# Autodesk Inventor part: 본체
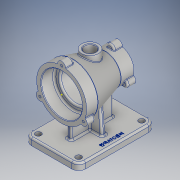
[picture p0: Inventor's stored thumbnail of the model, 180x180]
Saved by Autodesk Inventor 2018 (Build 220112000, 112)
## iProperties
Created: 2020-03
Part Number: 본체
Material: 알루미늄 6061
Document SubType Name: Modeling
Designer: Administrator
Density: 2.7 g/cm^3
Appearance: 알루미늄 - 평지
Mass: 1020.21 g
Surface Area: 863.968 cm^2
Volume: 377.855 cm^3
Author: Administrator
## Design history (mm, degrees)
sketch "스케치1"
  geometry: L1 (0, 0)-(0, 44); L2 (0, 44)-(-20, 44); L3 (-20, 44)-(-82.164, 27.5); L4 (-82.164, 27.5)-(-100, 27.5); L5 (-100, 27.5)-(-100, 0); L6 (-100, 0)-(0, 0)
  constraints: 12 end point, 3 perpendicular, 1 parallel, 1 vertical
  dimensions: "d0" = 20 distance from line of L2.end L1; "d1" = 100 distance between parallel lines of L5 L1; "d2" = 88 diameter of L2 L6; "d3" = 55 diameter of L4 L6
revolve "회전1" sketch "스케치1" stored, may be unused: angle "d4" = 90 deg
sketch "스케치2"
  geometry: L1 (0, 0)-(23, 0); L2 (23, 0)-(23, 36); L3 (23, 36)-(0, 36); L4 (0, 36)-(0, 0); L5 (23, 0)-(70, 0); L6 (70, 0)-(70, 26); L7 (70, 26)-(23, 26); L8 (23, 26)-(23, 0); L9 (100, 27.5)-(100, -27.5) reference; L10 (70, 0)-(100, 0); L11 (100, 0)-(100, 20); L12 (100, 20)-(70, 20); L13 (70, 20)-(70, 0)
  constraints: 24 end point, 6 parallel, 3 horizontal, 3 perpendicular, 1 point on line
  dimensions: "d5" = 23 distance of L2.end L3.end; "d6" = 30 distance of L11.end L12.end; "d7" = 72 diameter of L3 L1; "d8" = 52 diameter of L7 L5; "d9" = 40 diameter of L12 L10
revolve "회전2" sketch "스케치2" stored, may be unused: angle "d10" = 90 deg
chamfer "모따기1" distance "d11" = 1; stored, may be unused: second distance "d12" = 2, angle "d13" = 45 deg
fillet "모깎기1" dims "d14" = 3
fillet "모깎기2" dims "d15" = 3
node "작업 평면1"
sketch "스케치3"
  geometry: L1 (0, -44)-(0, 44) reference; L2 (-100, -27.5)-(-100, 27.5) reference; L3 (0, 0)-(-100, 0); L4 (17.5, 47.5)-(-117.5, 47.5); L5 (-117.5, 47.5)-(-117.5, -47.5); L6 (-117.5, -47.5)-(17.5, -47.5); L7 (17.5, -47.5)-(17.5, 47.5); L8 (17.5, 47.5)-(-117.5, -47.5); L9 (-117.5, 47.5)-(17.5, -47.5); 2 further points
  constraints: 14 end point, 6 midpoint, 2 parallel, 1 horizontal, 1 perpendicular
  dimensions: "d17" = 135 distance of L5.end L6.end; "d18" = 95 distance of L4.end L5.end
extrude "돌출1" join sketch "스케치3" distance "d19" = 12; taper "d20" = 0 deg
sketch "스케치4"
  geometry: L1 (117.5, 47.5)-(-17.5, 47.5) reference; L2 (-17.5, 47.5)-(-17.5, -47.5) reference; L3 (-17.5, -47.5)-(117.5, -47.5) reference; L4 (-17.5, 47.5)-(-17.5, -47.5) reference; L5 (117.5, 47.5)-(-17.5, 47.5) reference; L6 (117.5, -47.5)-(117.5, 47.5) reference; L7 (13, -4)-(87, -4); L8 (87, -4)-(87, 4); L9 (87, 4)-(13, 4); L10 (13, 4)-(13, -4); L11 (13, -4)-(87, 4); L12 (87, -4)-(13, 4); 3 further points
  constraints: 12 end point, 3 midpoint, 2 parallel, 1 horizontal, 1 horizontal alignment, 1 perpendicular
  dimensions: "d21" = 67.5 distance from line of point (50, 0) L6; "d22" = 8 distance of L7.end L8.end; "d23" = 74 distance of L8.end L9.end
extrude "돌출2" join sketch "스케치4" stored distance "d24" = 12; taper "d25" = 0 deg
node "작업 평면2"
feature "리브1" dims "d28" = 1, "d29" = 8, "d30" = 0, "d31" = 0, "d32" = 1, "d33" = 1
node "작업 평면3"
sketch "스케치6"
  geometry: L1 (17.5, -47.5)-(17.5, 47.5) reference; L2 (17.5, 0)-(-117.5, 0); L3 (-117.5, 47.5)-(-117.5, -47.5) reference; C1 r 15 at (-50, 0); 1 further point
  constraints: 3 midpoint, 2 end point, 1 centre point
  dimensions: "d35" = 30 diameter of C1
extrude "돌출3" join sketch "스케치6" stored distance "d36" = 12; taper "d37" = 0 deg
sketch "스케치7"
  geometry: C1 r 15 at (0, 0) reference; C2 r 10 at (0, 0); 1 further point
  constraints: 1 centre point, 1 coincident
  dimensions: "d38" = 20 diameter of C2
extrude "돌출4" cut sketch "스케치7" stored distance "d39" = 12; taper "d40" = 0 deg; dims "d17" = 135, "d18" = 95, "d154" = 3
chamfer "모따기2" distance "d41" = 1; stored, may be unused: second distance "d42" = 2, angle "d43" = 45 deg
fillet "모깎기3" dims "d44" = 12
fillet "모깎기4" dims "d45" = 3
fillet "모깎기5" dims "d46" = 3
fillet "모깎기6" dims "d47" = 3
fillet "모깎기7" dims "d48" = 3
fillet "모깎기8" dims "d49" = 3
fillet "모깎기9" dims "d50" = 3
fillet "모깎기10" dims "d51" = 3
fillet "모깎기11" dims "d52" = 3
fillet "모깎기12" dims "d53" = 3
sketch "스케치8"
  geometry: A1 r 12 centre (105.5, 35.5) between (117.5, 35.5) and (105.5, 47.5) reference; A2 r 12 centre (105.5, -35.5) between (105.5, -47.5) and (117.5, -35.5) reference; A3 r 12 centre (-5.5, -35.5) between (-17.5, -35.5) and (-5.5, -47.5) reference; A4 r 12 centre (-5.5, 35.5) between (-5.5, 47.5) and (-17.5, 35.5) reference; 5 further points
  constraints: 4 coincident
hole "구멍1" sketch "스케치8" at (105.5, 35.5), (105.5, -35.5), (-5.5, -35.5), (-5.5, 35.5) diameter "d54" = 10; stored, may be unused: countersink angle "d58" = 90 deg, drill point angle "d60" = 118 deg; dims "d55" = 6, "d56" = 4, "d57" = 2, "d59" = 8
sketch "스케치9"
  geometry: C1 r 44 at (0, 0); A1 r 43.9 centre (0, 0) between (6.566, -43.406) and (-6.566, -43.406) reference; A2 r 7 centre (0, 43.9) between (6.978, 43.342) and (-6.978, 43.342); 2 further points
  constraints: 6 point on circle, 2 centre point, 1 coincident, 1 vertical alignment
  dimensions: "d61" = 88 diameter of C1; "d62" = 14 diameter of A2
extrude "돌출5" join sketch "스케치9" distance "d63" = 15; taper "d64" = 0 deg
sketch "스케치10"
  geometry: A1 r 7 centre (0, 0) between (6.985, -0.458) and (-6.985, -0.458) reference; 2 further points
  constraints: 1 coincident
hole "구멍2" sketch "스케치10" at (0, 0) diameter "d68" = 4.134; stored, may be unused: countersink angle "d72" = 90 deg, drill point angle "d74" = 118 deg; dims "d69" = 9, "d70" = 4, "d71" = 2, "d73" = 11
fillet "모깎기13" dims "d78" = 1
sketch "스케치11"
  geometry: A1 r 27.5 centre (0, 0) between (6.943, 26.609) and (-6.943, 26.609); A2 r 27.5 centre (0, 0) between (6.311, -26.766) and (-6.311, -26.766) reference; A3 r 7 centre (0, 27.5) between (6.943, 26.609) and (-6.943, 26.609); 1 further point
  constraints: 6 point on circle, 2 centre point, 1 coincident
  dimensions: "d81" = 7 radius of A3
extrude "돌출6" join sketch "스케치11" distance "d82" = 15; taper "d83" = 0 deg
sketch "스케치12"
  geometry: A1 r 7 centre (0, 0) between (6.943, -0.891) and (-6.943, -0.891) reference; 2 further points
  constraints: 1 coincident
hole "구멍3" sketch "스케치12" at (0, 0) diameter "d87" = 4.134; stored, may be unused: countersink angle "d91" = 90 deg, drill point angle "d93" = 118 deg; dims "d88" = 9, "d89" = 4, "d90" = 2, "d92" = 11
fillet "모깎기14" dims "d97" = 3
fillet "모깎기15" dims "d98" = 3
fillet "모깎기16" dims "d99" = 1
sketch "스케치13"
  geometry: L1 (-17.5, 35.5)-(-17.5, -35.5) reference; L2 (-17.5, 0)-(118.541, 0); L3 (-5.5, -47.5)-(105.5, -47.5) reference; 3 further points
  constraints: 2 end point, 2 midpoint, 1 horizontal, 1 vertical alignment, 1 other
  dimensions: "d100" = 10 distance from line of point (50.521, -37.5) L3
feature "엠보싱1" sketch "스케치13" dims "d5" = 23, "d6" = 30, "d7" = 72, "d8" = 52, "d9" = 40, "d101" = 0.5, "d102" = 0
sketch "스케치14"
  geometry: 1 further point
sketch "스케치15"
  geometry: 1 further point
sketch "스케치16"
  geometry: L1 (0, 0)-(0, 44); L2 (0, 44)-(20, 44); L3 (20, 44)-(77, 27.5); L4 (77, 27.5)-(100, 27.5); L5 (100, 27.5)-(100, 0); L6 (100, 0)-(0, 0)
  constraints: 12 end point, 3 perpendicular, 1 parallel, 1 vertical
  dimensions: "d103" = 20 distance of L1.end L2.end; "d104" = 100 distance between parallel lines of L5 L1; "d105" = 77 distance from line of L3.end L1; "d106" = 88 diameter of L2 L6; "d107" = 55 diameter of L4 L6
revolve "회전3" sketch "스케치16" stored, may be unused: angle "d108" = 90 deg
sketch "스케치17"
  geometry: L1 (13, -4)-(87, -4); L2 (87, -4)-(87, 4); L3 (87, 4)-(13, 4); L4 (13, 4)-(13, -4); L5 (13, -4)-(87, 4); L6 (87, -4)-(13, 4); L7 (117.5, -35.5)-(117.5, 35.5) reference; 3 further points
  constraints: 12 end point, 3 midpoint, 2 parallel, 1 horizontal, 1 horizontal alignment, 1 perpendicular
  dimensions: "d109" = 67.5 distance from line of point (50, 0) L7; "d110" = 74 distance of L2.end L3.end; "d111" = 8 distance of L1.end L2.end
extrude "돌출7" join sketch "스케치17" stored distance "d112" = 10; taper "d113" = 0 deg
node "작업 평면4"
sketch "스케치18"
  geometry: L1 (71.029, 12.5)-(71.029, 12) reference; L2 (71.029, 12)-(80, 12) reference; L3 (83, 9)-(83, 0) reference; L4 (83, 0)-(-12, 0) reference; L5 (-12, 0)-(-12, 9) reference; L6 (-9, 12)-(31.5, 12) reference; L7 (31.5, 12)-(31.5, 51.911) reference; L8 (39.5, 51.911)-(39.5, 12) reference; L9 (39.5, 12)-(70.615, 12) reference; L10 (70.615, 12)-(70.615, 12.5) reference; L11 (70.615, 12.5)-(71.029, 12.5) reference; L12 (0, 12)-(71, 12) reference; L13 (60.5, 12)-(56.427, 58.553); L14 (71, 0)-(0, 0) reference; L15 (35.5, 0)-(35.5, 87); A1 r 3 centre (80, 9) between (83, 9) and (80, 12) reference; A2 r 3 centre (-9, 9) between (-9, 12) and (-12, 9) reference; A3 r 35.316 centre (35.5, 87) between (39.5, 51.911) and (31.5, 51.911) reference; 1 further point
  constraints: 4 end point, 1 midpoint, 1 point on circle, 1 point on line, 1 vertical
  dimensions: "d114" = 25 distance from line of L13.start L15; "d115" = 95 deg angle of L13 L9
feature "리브2" sketch "스케치18" dims "d116" = 1, "d117" = 8, "d118" = 0, "d119" = 0, "d120" = 1, "d121" = 1
sketch "스케치19"
  geometry: L1 (0, 0)-(23, 0); L2 (23, 0)-(23, 36); L3 (23, 36)-(0, 36); L4 (0, 36)-(0, 0); L5 (23, 0)-(70, 0); L6 (70, 26)-(23, 26); L7 (23, 26)-(23, 0); L8 (70, 26)-(70, 0); L9 (100, -27.5)-(100, 27.5) reference; L10 (70, 0)-(100, 0); L11 (100, 0)-(100, 20); L12 (100, 20)-(70, 20); L13 (70, 20)-(70, 0)
  constraints: 24 end point, 5 parallel, 3 horizontal, 2 perpendicular, 1 point on line, 1 vertical
  dimensions: "d122" = 23 distance of L2.end L3.end; "d124" = 72 diameter of L3 L1; "d125" = 52 diameter of L6 L5; "d126" = 30 distance of L11.end L12.end; "d127" = 40 diameter of L12 L10
revolve "회전4" sketch "스케치19" stored, may be unused: angle "d128" = 90 deg
node "작업 평면5"
sketch "스케치20"
  geometry: L1 (0, 0)-(-100, 0); L2 (-100, 27.5)-(-100, -27.5) reference; C1 r 15 at (-50, 0)
  constraints: 2 end point, 2 midpoint, 1 centre point
  dimensions: "d130" = 30 diameter of C1
extrude "돌출8" join sketch "스케치20" stored distance "d131" = 10; taper "d132" = 0 deg
sketch "스케치21"
  geometry: C1 r 15 at (0, 0) reference; C2 r 10 at (0, 0); 1 further point
  constraints: 1 centre point, 1 coincident
  dimensions: "d133" = 20 diameter of C2
extrude "돌출9" cut sketch "스케치21" stored distance "d134" = 10; taper "d135" = 0 deg
sketch "스케치22"
  geometry: C1 r 7 at (0, 44); A1 r 44 centre (0, 0) between (-4, -43.818) and (4, -43.818); A2 r 44 centre (0, 0) between (4, -43.818) and (-4, -43.818) reference; 1 further point
  constraints: 2 centre point, 1 coincident, 1 point on circle
  dimensions: "d136" = 88 diameter of A1; "d137" = 14 diameter of C1
extrude "돌출10" join sketch "스케치22" distance "d138" = 15; taper "d139" = 0 deg
sketch "스케치23"
  geometry: C1 r 7 at (0, 27.5); 2 further points
  constraints: 2 vertical alignment, 1 centre point, 1 other
  dimensions: "d143" = 14 diameter of C1
extrude "돌출11" join sketch "스케치23" distance "d144" = 15; taper "d145" = 0 deg
chamfer "모따기3" distance "d149" = 1; stored, may be unused: second distance "d150" = 2, angle "d151" = 45 deg
fillet "모깎기17" dims "d152" = 3
fillet "모깎기18" dims "d153" = 1
fillet "모깎기19" dims "d154" = 3
fillet "모깎기20" dims "d155" = 3
fillet "모깎기21" dims "d156" = 3
fillet "모깎기22" dims "d157" = 3
fillet "모깎기23" dims "d158" = 3
fillet "모깎기24" dims "d159" = 3
fillet "모깎기25" dims "d160" = 3
fillet "모깎기26" dims "d161" = 3
fillet "모깎기27" dims "d162" = 3
sketch "스케치24"
  geometry: 2 further points
hole "구멍4" sketch "스케치24" at (0, 0) diameter "d163" = 4.134; stored, may be unused: countersink angle "d167" = 90 deg, drill point angle "d169" = 118 deg; dims "d164" = 9, "d165" = 4, "d166" = 2, "d168" = 11
sketch "스케치25"
  geometry: A1 r 7 centre (0, 0) between (6.943, -0.891) and (-6.943, -0.891) reference; 2 further points
  constraints: 1 coincident
hole "구멍5" sketch "스케치25" at (0, 0) diameter "d173" = 4.134; stored, may be unused: countersink angle "d177" = 90 deg, drill point angle "d179" = 118 deg; dims "d174" = 9, "d175" = 4, "d176" = 2, "d178" = 11
fillet "모깎기28" dims "d183" = 3
fillet "모깎기29" dims "d184" = 3
fillet "모깎기30" dims "d185" = 1
node "솔리드1"
mirror "미러1"
pattern_circular "원형 패턴1" dims angle "d66" = 360 deg
pattern_circular "원형 패턴2" dims angle "d76" = 360 deg
pattern_circular "원형 패턴3" dims angle "d85" = 360 deg
pattern_circular "원형 패턴4" dims angle "d95" = 360 deg
mirror "미러2"
pattern_circular "원형 패턴5" dims angle "d141" = 360 deg
pattern_circular "원형 패턴6" dims angle "d147" = 360 deg
pattern_circular "원형 패턴7" dims angle "d171" = 360 deg
pattern_circular "원형 패턴8" dims angle "d181" = 360 deg
node "투영된 루프1"
sketch "스케치5"
  geometry: L1 (95, 12)-(95, 0) reference; L2 (95, 0)-(0, 0) reference; L3 (0, 0)-(0, 12) reference; L4 (0, 12)-(95, 12) reference; L5 (95, 12)-(0, 12) reference; L6 (72.5, 12)-(68.501, 57.714); L7 (95, 0)-(0, 0) reference; L8 (47.5, 0)-(47.5, 61); 2 further points
  constraints: 4 end point, 1 midpoint, 1 point on line, 1 vertical, 1 vertical alignment, 1 other
  dimensions: "d26" = 25 horizontal distance of L6.start L8.start
node "투영된 루프2"
node "절단 모서리 투영1"
node "절단 모서리 투영2"
other parameters: "d16" = -87, "d34" = 45, "d129" = 45
